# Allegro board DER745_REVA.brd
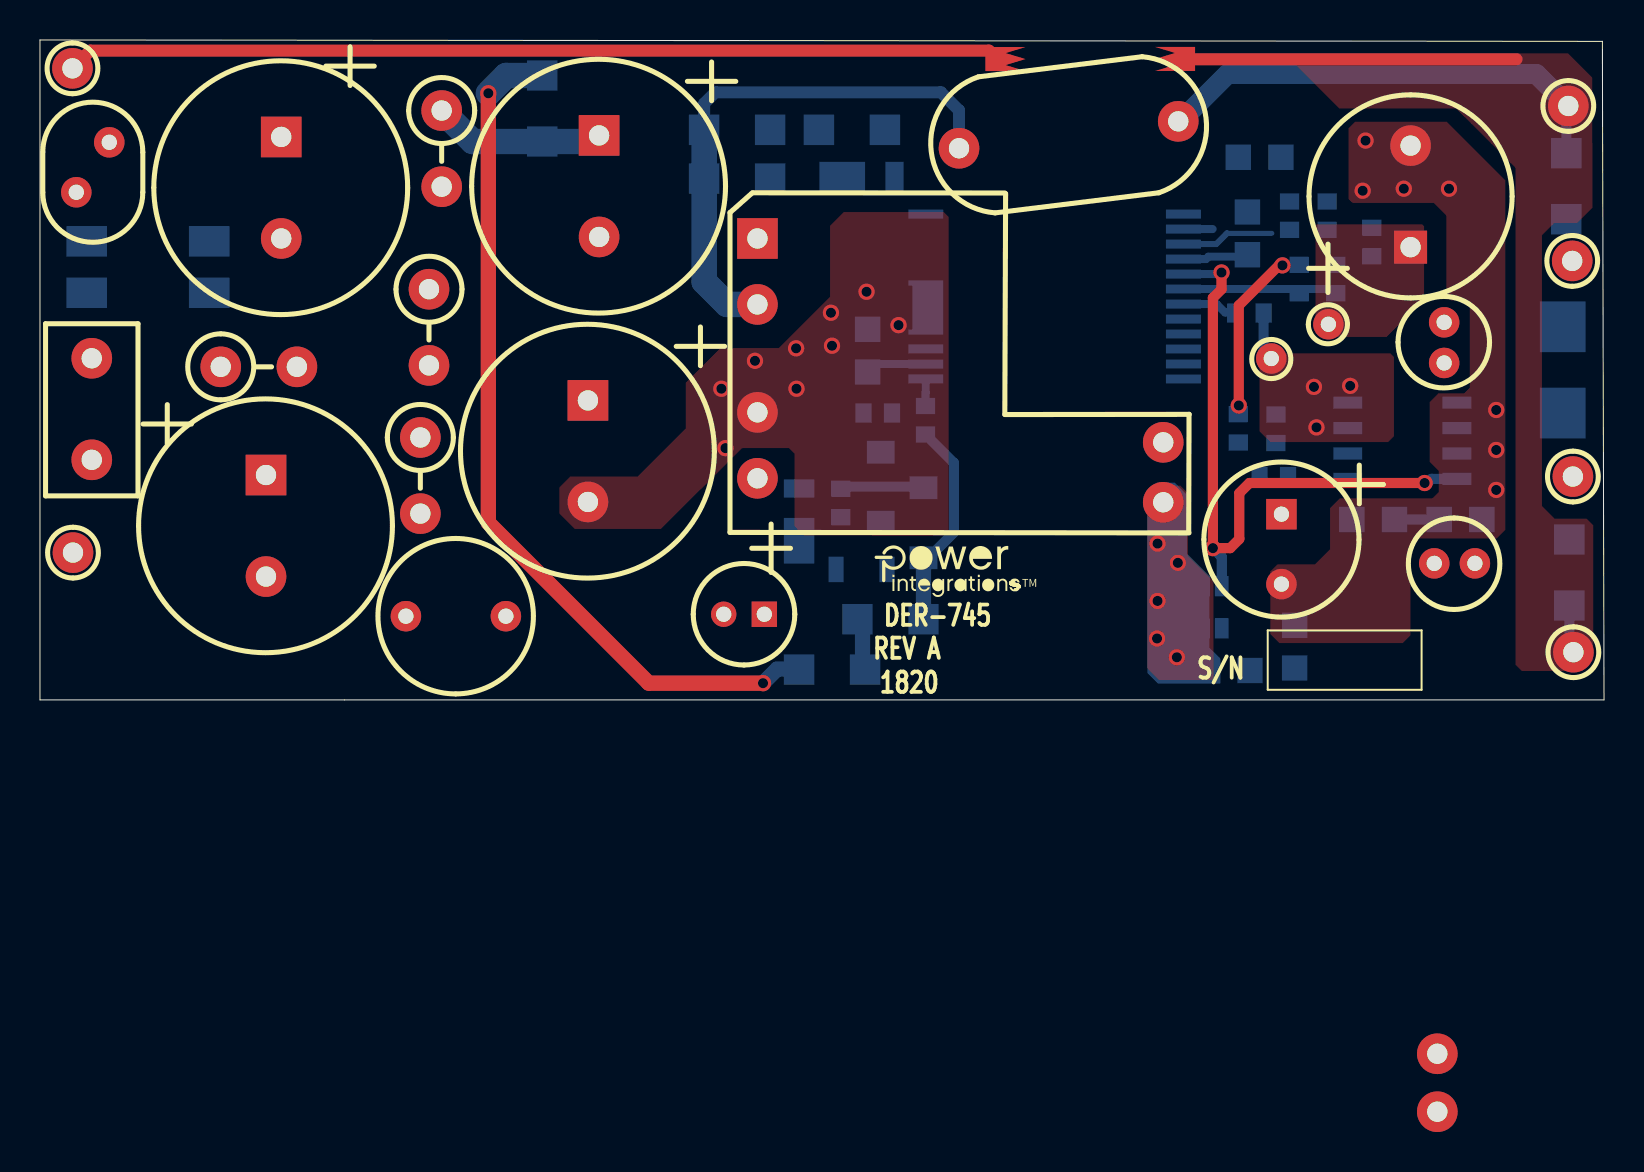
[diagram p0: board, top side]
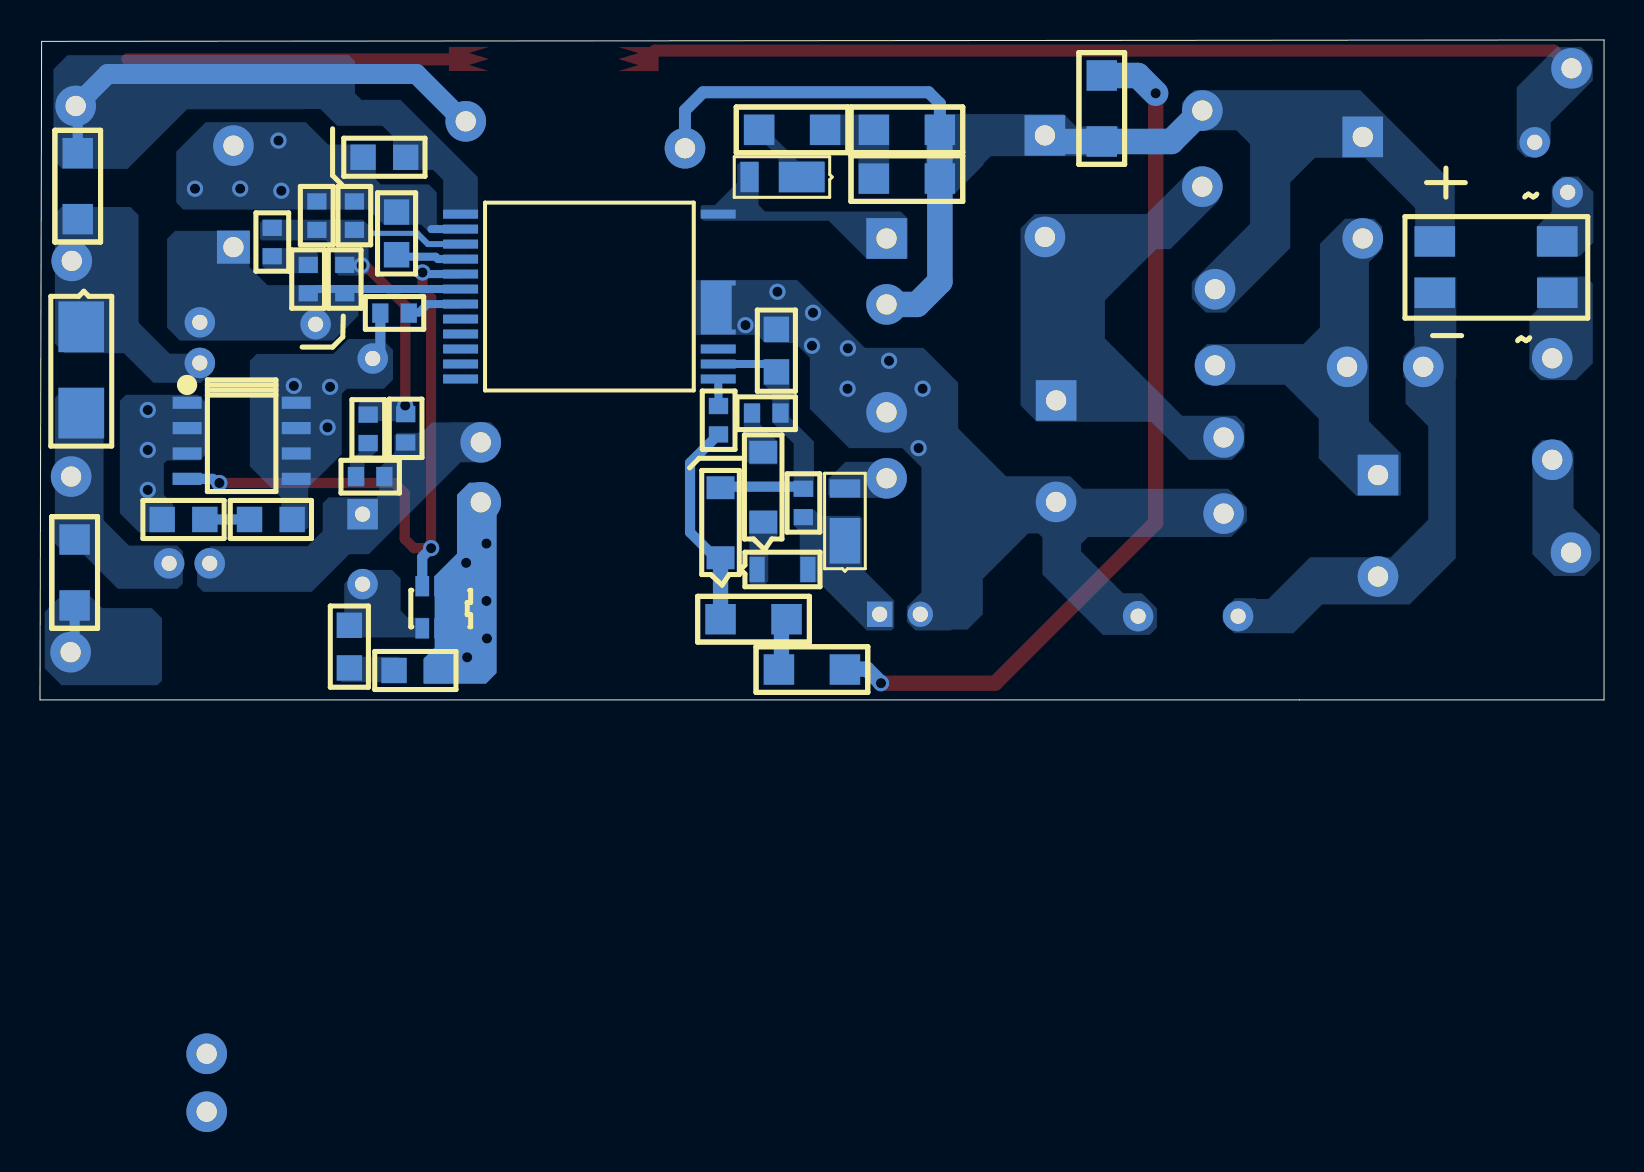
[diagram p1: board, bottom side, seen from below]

Outline 78.24 x 33.02 mm; copper layers: TOP, BOTTOM. Coordinates in mm from the lower left corner of the outline.
Outline path: 0,33.02 0,0 78.24,0 78.16,32.95 0,33.02

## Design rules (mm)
constraint set DEFAULT: min track width 0.508

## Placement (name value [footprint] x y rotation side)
BR1  B10S-G  [PISMSOIC4]  2.34 20.37 90 bottom
C1  22 uF  [PIPOLCAPCLYD500LS200040]  12.07 28.17 270 top
C2  22 uF  [PIPOLCAPCLYD500LS200040]  11.31 11.25 270 top
C3  22 uF  [PIPOLCAPCLYD500LS200040]  27.97 28.24 270 top
C4  22 uF  [PIPOLCAPCLYD500LS200040]  27.41 14.99 270 top
C5  1000 pF  [PISMC1206]  33.22 26.09 0 bottom
C6  22  uF  [PIPOLCAPCLYD200LS80030]  36.23 4.29 180 top
C7  4.7 uF  [PISMC0805]  41.4 16.41 90 bottom
C8  470 pF  [PINPCAPRAD455X275435030]  56.94 28.95 187 top
C9  1 nF  [PISMC0805]  65.62 9.03 0 bottom
C10  680 uF  [PIPOLCAPCYLD400LS200040]  68.56 22.65 90 top
C11  1 nF  [PISMC0805]  62.76 1.6 90 bottom
C12  560 uF  [PIPOLCAPCYLD315LS138D030]  62.1 9.29 270 top
C13  2.2 uF  [PISMC0805]  60.4 24.41 270 bottom
C14  330 pF  [PISMC0603]  62.51 24.94 270 bottom
C15  2.2 nF  [PISMC0603]  66.62 22.2 90 bottom
C16  2.2 nF  [PISMC0603]  61.82 12.85 90 bottom
C17  2.2 uF  [PISMC1206]  76.35 24.05 90 bottom
C18  2.2 uF  [PISMC1206]  76.5 8.03 270 bottom
D1  DFLR1600-7  [PISMDDFLR120012]  40.11 26.16 180 bottom
D2  BAV21W-7-F  [PI_SM_SOD-123_12]  44.2 7.11 90 bottom
D3  DFLR1200-7  [PISMDDFLR120012]  37.97 7.94 270 bottom
D4  BAV21WS-7-F  [PISMSOD323]  42.37 6.53 180 bottom
F1  1 A  [PI_RST_MICROFUSE]  2.59 12.01 90 top
FL1  Hole_30mils  [PI_HOLE_30MIL]  64.45 18.8 270 top
FL2  Hole_30mils  [PI_HOLE_30MIL]  61.59 17.08 0 top
L1  330 uH  [PICHOKETOKINVD345H453LS197D030]  18.31 4.19 0 top
L2  10 uH  [PI_CHOKE_TOKIN_1]  70.24 18.89 270 top
L3  10 uH  [PI_CHOKE_TOKIN_1]  69.75 6.83 0 top
LINE  WHT  [PITPKEYSTONE100X100]  1.63 31.6 0 top
NEUTRAL  RED  [PITPKEYSTONE100X100]  1.65 7.37 0 top
NOREF  -  []  -213.36 -144.78 0 top
NOREF#2  -  []  -135.54 54.23 0 top
NOREF#3  -  []  0 0 0 top
NOREF#4  -  []  41.2 7.62 0 top
NOREF#5  -  []  78.16 32.95 270.1 top
Q1  AO6420  [PISMSOT236_SHORT1256]  57.24 5.69 0 bottom
Q2  AO4486  [PISMSO8]  70.88 14.87 270 bottom
R1  620 k  [PI12WVRESD180LS150D040]  19.46 20.55 270 top
R2  620 k  [PI12WVRESD180LS150D040]  9.04 16.67 0 top
R3  620 k  [PI12WVRESD180LS150D040]  20.1 29.49 270 top
R4  620 k  [PI12WVRESD180LS150D040]  19.03 13.13 270 top
R5  3.30 M  [PISMR1206]  25.12 27.94 90 bottom
R6  3.30 M  [PISMR1206]  37.97 1.52 0 bottom
R7  3 M  [PISMR1206]  40.89 4.04 0 bottom
R8  200 k  [PISMR1206]  33.22 28.52 0 bottom
R9  68  [PISMR1206]  38.96 28.52 0 bottom
R10  100 k  [PISMR0603]  44.3 13.28 90 bottom
R11  6.2 k  [PISMR0603]  40.06 9.14 90 bottom
R12  36  [PISMR0603]  42.62 14.35 180 bottom
R13  30  [PISMR0805]  69.99 9.03 0 bottom
R14  62  [PISMR0805]  58.39 1.47 0 bottom
R15  47  [PISMR0603]  59.79 19.35 0 bottom
R16  33.2 k  [PISMR0603]  64.39 24.94 270 bottom
R17  0.02  [PISMR0805]  62.08 27.15 180 bottom
R18  100  [PISMR0603]  64.82 21.77 270 bottom
R19  1.20 M  [PISMR0603]  62.99 21.77 270 bottom
R20  100  [PISMR0603]  62.43 11.18 180 bottom
R21  133 k  [PISMR0603]  59.94 14.3 270 bottom
RT1  10  [PI_RAD_276DX197T_LS100D025]  2.64 25.4 90 top
T1  EE1621  [PI_BOBBIN_EE1621_8P]  35.89 23.09 0 top
U1  INN3672C  [PI_IC_INSOP_24D]  57.2 24.31 180 bottom
UNK5V  RED  [PITPKEYSTONE100X100]  76.68 11.18 0 top
UNK5VRTN  WHT  [PITPKEYSTONE100X100]  76.71 2.39 0 top
UNK12V  YEL  [PITPKEYSTONE100X100]  76.65 21.97 0 top
UNK12VRTN  BLK  [PITPKEYSTONE100X100]  76.45 29.72 0 top
VR1  MMSZ5231B-7-F  [PI_SM_SOD-123_12]  42.06 8.89 90 bottom
VR2  SMAZ8V2-13-F  [PISMDO214AC12]  76.17 18.67 270 bottom

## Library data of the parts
BR1 = DIODE BRIDGE_~~+-: alternate symbols: (pi_sm_soic4_slot)
C1-C4 = CAP POL: alternate symbols: (pipolcapclyd500ls200040630lh)
C5 C7-C9 C11 C13-C18 = CAP NP
C6 = CAP POL: alternate symbols: (pipolcapclyd200ls80030h)
C10 = CAP POL
C12 = CAP POL: alternate symbols: (pipolcapcyld315ls138d030h)
D1-D4 = DIODE
F1 = FUSE: alternate symbols: (pirstmicrofusehoz)
FL1 FL2 = FlyingLead
L1-L3 = INDUCTOR
LINE NEUTRAL UNK5V UNK5VRTN UNK12V UNK12VRTN = TESTPOINT
Q1 = FET_N_DGS
Q2 = FET_N_SGD_123_4_5678
R1-R4 = R: alternate symbols: (pi12wvresd180ls200d040,pi12wvresd180ls250d040,pi12wresd180ls675d040)
R5-R21 = R
RT1 = THERMISTOR
T1 = BEE16_8P/GENERIC
U1 = DEV_Inno3EP
VR1 VR2 = DIODE_ZENER

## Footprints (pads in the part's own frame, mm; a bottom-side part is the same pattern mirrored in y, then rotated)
PI12WVRESD180LS150D040
  round 2.032 hole 1.016: 1(0,0) 2(3.81,0)
PI_BOBBIN_EE1621_8P
  rect 2.032x2.032 hole 1.016: 1(0,0)
  round 2.032 hole 1.016: 2(0,-3.3) 3(0,-8.7) 4(0,-12) 5(20.3,-13.2) 6(20.3,-10.2) 7(34.011,-43.692) 8(34.011,-40.792)
PI_CHOKE_TOKIN_1
  round 1.524 hole 0.762: 1(0,0) 2(2.032,0)
PI_HOLE_30MIL
  round 1.524 hole 0.762: 1(0,0)
PI_IC_INSOP_24D
  rect 1.75x0.45 smd: 1(0,0) 2(0,-0.749) 3(0,-1.501) 4(0,-2.25) 5(0,-3) 6(0,-3.749) 7(0,-4.501) 8(0,-5.25) 9(0,-6) 10(0,-6.749) 11(0,-7.501) 12(0,-8.25) 13(12.89,-8.25) 14(12.89,-7.501) 15(12.89,-6.749) 24(12.89,0)
  custom 0.437x0.437 smd: 16(12.89,-4.671)
PI_RAD_276DX197T_LS100D025
  round 1.524 hole 0.762: 1(0,0.825) 2(2.5,-0.825)
PI_RST_MICROFUSE
  round 2.032 hole 1.016: 1(0,0) 2(5.08,0)
PI_SM_SOD-123_12
  rect 1.143x1.397 smd: 1(0,0) 2(3.505,0)
PICHOKETOKINVD345H453LS197D030
  round 1.524 hole 0.762: 1(0,0) 2(5.001,0)
PINPCAPRAD455X275435030
  round 2.032 hole 1.016: 1(0,0) 2(11.049,0)
PIPOLCAPCLYD200LS80030
  rect 1.27x1.27 hole 0.762: 1(0,0)
  round 1.27 hole 0.762: 2(2.032,0)
PIPOLCAPCLYD500LS200040
  rect 2.032x2.032 hole 1.016: 1(0,0)
  round 2.032 hole 1.016: 2(5.08,0)
PIPOLCAPCYLD315LS138D030
  rect 1.524x1.524 hole 0.762: 1(0,0)
  round 1.524 hole 0.762: 2(3.5,0)
PIPOLCAPCYLD400LS200040
  rect 1.651x1.651 hole 1.016: 1(0,0)
  round 2.032 hole 1.016: 2(5.08,0)
PISMC0603
  rect 0.813x0.965 smd: 1(0,0) 2(1.422,0)
PISMC0805
  rect 1.27x1.27 smd: 1(0,0) 2(2.134,0)
PISMC1206
  rect 1.524x1.524 smd: 1(0,0) 2(3.302,0)
PISMDDFLR120012
  rect 2.286x1.524 smd: 1(-0.025,0)
  rect 0.914x1.524 smd: 2(-2.642,0)
PISMDO214AC12
  rect 2.54x2.286 smd: 1(0,0) 2(4.318,0)
PISMR0603
  rect 0.813x0.965 smd: 1(0,0) 2(1.422,0)
PISMR0805
  rect 1.27x1.27 smd: 1(0,0) 2(2.134,0)
PISMR1206
  rect 1.524x1.524 smd: 1(0,0) 2(3.302,0)
PISMSO8
  rect 0.61x1.448 smd: 1(0,0) 2(1.27,0) 3(2.54,0) 4(3.81,0) 5(3.81,5.461) 6(2.54,5.461) 7(1.27,5.461) 8(0,5.461)
PISMSOD323
  rect 0.762x1.27 smd: 1(0,0) 2(2.54,0)
PISMSOIC4
  rect 1.524x2.032 smd: 1(0,0) 2(2.57,0) 3(2.57,6.129) 4(0,6.129)
PISMSOT236_SHORT1256
  rect 0.686x1.016 smd: (0,2.108) (0.94,0) (0.94,2.108) 1(0,0) 3(1.88,0) 4(1.88,2.108)
PITPKEYSTONE100X100
  round 2.032 hole 1.016: 1(0,0)

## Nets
NC8: U1.8
NC9: U1.9
NC10: U1.10
NC11: U1.11
NC12: U1.12
NC15: U1.15
N11050040: C17.1 L2.2 UNK12V.1 VR2.1
N11050316: BR1.3 C1.1 C3.1 C5.1 C8.2 R1.1 R3.1 R5.1 R8.1 T1.2
N11050566: C5.2 R8.2 R9.1
N11050744: BR1.1 F1.2
N11050756: BR1.2 RT1.1
N11050878: D1.1 R9.2
N11050972: C14.2 C15.2 C16.2 R16.2 R19.1 R21.1 U1.3
N11051112: D1.2 T1.1 U1.24
N11051256: R15.1 U1.7
N11051362: C6.1 D3.1 D4.2 R11.1
N11051472: D4.1 VR1.1
N11051658: C7.1 D2.2 R11.2 R12.2 U1.14
N11051742: C4.2 C6.2 C7.2 L1.2 R4.2 T1.3 U1.16
N11051898: LINE.1 RT1.2
N11051902: F1.1 NEUTRAL.1
N11062996: C9.1 FL2.1 Q2.5 Q2.6 Q2.7 Q2.8 R15.2
N11063539: C10.1 FL1.1 L2.1 R18.2 R19.2 U1.6
N11067713: R10.2 U1.13(VPIN)
N11070094: C8.1 C17.2 C18.2 R17.2 U1.1 UNK5VRTN.1 UNK12VRTN.1
N11075733: C11.1 R14.2
N11083581: C10.2 C11.2 C12.2 C13.1 C14.1 Q1.4(S) Q2.1 Q2.2 Q2.3(S3) R13.2 R16.1 R17.1 U1.2
N11083861: Q1.3 Q2.4 U1.5
N11101991: C12.1 L3.1 R20.2 R21.2 T1.6
N11104379: R12.1 VR1.2
N11115969: C9.2 R13.1
N11124964: D3.2 T1.4
N11129285: Q1.1 R14.1 T1.5
N11132220: C13.2 U1.4
N11135486: C15.1 R18.1
N11135939: C18.1 L3.2 UNK5V.1 VR2.2
N11142568: C16.1 R20.1
N11149792: BR1.4 C2.2 L1.1 R2.1
N11149826: C1.2 C2.1 R1.2 R2.2
N11150103: C3.2 C4.1 R3.2 R4.1
N11155318: R5.2 R6.1
N11155322: R6.2 R7.1
N11155751: D2.1 R7.2 R10.1

Pads without a net: T1 7 8

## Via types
v1: diameter 0.813, hole 0.508, TOP to BOTTOM, 31 vias

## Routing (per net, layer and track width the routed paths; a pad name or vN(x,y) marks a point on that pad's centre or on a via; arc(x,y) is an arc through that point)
N11050316: length 35.9
  BOTTOM w0.6: R8.1 33.22,29.84 33.79,30.4 45.07,30.4 45.97,29.5 C8.2
  BOTTOM w1.27: R3.1 21.64,27.94 R5.1 27.66,27.94 C3.1 ; T1.2 34.36,19.79 33.22,20.93 C5.1 R8.1
N11050972: length 12.7
  TOP w0.508: v1(62.15,21.74) 61.98,21.74 59.97,19.74 v1(59.97,14.73)
  BOTTOM w0.25: 61.62,23.34 59.37,23.34
  BOTTOM w0.3: 59.37,23.34 58.84,22.81 U1.3
N11051256: length 2.8
  BOTTOM w0.4: R15.1 59.77,19.38 59.29,19.38 58.86,19.81 U1.7
N11051658: length 7.3
  BOTTOM w0.4: U1.14 41.8,16.81 C7.1
  BOTTOM w0.508: D2.2 44.15,10.67 40.16,10.67 R11.2
N11051742:
  vias: v1(34.09,15.57) v1(34.29,12.6) v1(35.77,16.97) v1(37.82,17.59) v1(37.84,15.57) v1(39.57,19.37) v1(39.62,17.72) v1(41.35,20.42) v1(42.95,18.75)
N11051898: length 46.8
  TOP w0.6: LINE.1 2.51,32.49 47.47,32.49 47.85,32.11
N11062996: length 2.4
  BOTTOM w0.508: R15.2 61.21,17.46 FL2.1
  vias: v1(63.73,15.66) v1(63.86,13.64) v1(65.54,15.71)
N11063539: length 7.1
  BOTTOM w0.4: 64.31,20.56 U1.6
N11067713: length 1.4
  BOTTOM w0.4: U1.13 44.31,15.38 44.3,15.36 R10.2
N11070094: length 42.4
  TOP w0.6: 73.86,32.05 57.43,32.05
  BOTTOM w0.508: UNK12VRTN.1 76.35,29.62 C17.2 ; C18.2 76.5,2.59 UNK5VRTN.1
  BOTTOM w1: C8.1 57.04,28.95 59.41,31.32 74.85,31.32 UNK12VRTN.1
N11083581: length 1.5
  BOTTOM w0.4: U1.2 58.66,23.56
  vias: v1(66.17,25.48) v1(66.31,27.98) v1(68.22,25.58) v1(70.48,25.58) v1(72.85,14.51) v1(72.85,12.51) v1(72.85,10.51)
N11083861: length 33
  TOP w0.508: v1(69.27,10.85) 60.5,10.85 59.99,10.34 59.99,8.05 59.54,7.59 v1(58.67,7.59) 58.67,20.12 59.11,20.55 v1(59.11,21.39)
  BOTTOM w0.4: v1(59.11,21.39) 58.98,21.39 58.9,21.31 U1.5
  BOTTOM w0.508: v1(69.27,10.85) 69.4,10.85 69.61,11.06 Q2.4 ; v1(58.67,7.59) 59.12,7.15 Q1.3
N11115969: length 2.2
  BOTTOM w0.508: C9.2 R13.1
N11129285:
  vias: v1(55.91,7.82) v1(55.91,4.95) v1(55.88,3.07) v1(56.92,6.86) v1(56.87,2.13)
N11132220: length 3.3
  BOTTOM w0.4: C13.2 60.3,22.17 58.45,22.17 58.33,22.06 U1.4
N11155318: length 43.7
  TOP w0.762: v1(36.17,0.84) 30.45,0.84 22.43,8.86 v1(22.43,30.35)
  BOTTOM w0.762: v1(36.17,0.84) 36.87,1.54 37.95,1.54 R6.1
  BOTTOM w1.27: v1(22.43,30.35) 23.32,31.24 R5.2
N11155322: length 2.7
  BOTTOM w0.762: R7.1 41.15,3.78 41.15,1.65 R6.2
N11155751: length 10.6
  BOTTOM w0.508: D2.1 44.45,7.11 45.72,8.38 45.72,11.86 R10.1
  BOTTOM w0.762: D2.1 R7.2

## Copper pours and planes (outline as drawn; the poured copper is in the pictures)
N11050040 on BOTTOM: 70.15,17.32 71.75,17.32 73.3,18.87 73.3,24.26 73.71,24.66 77.17,24.66 77.5,24.33 77.5,17.83 77.01,17.35 74.04,17.35 72.57,15.88 70.18,15.88 69.72,16.33 69.72,16.89
N11050316 on BOTTOM: 24.31,28.7 26.42,28.7 27.03,29.31 33.88,29.31 33.93,29.26 33.93,25.3 32.51,25.3 31.04,26.77 31.04,26.85 30.68,27.2 24.43,27.2 24.28,27.36 24.28,28.68
N11050316 on BOTTOM: 20.5,30.51 12.19,30.51 7.47,25.78 7.47,22.17 9.45,22.17 9.45,24.61 11.96,27.13 14.45,27.13 15.7,25.88 15.7,22.61 18.92,19.38 19.91,19.38 20.62,20.09 20.62,20.9 17.7,23.83 17.7,27.81 18.39,28.5 20.95,28.5 21.11,28.65 21.11,29.9
N11050566 on BOTTOM: 39.73,29.29 39.73,27.76 38,27.76 37.3,27.06 37.3,25.36 37.26,25.32 35.79,25.32 35.76,25.35 35.76,29.29
N11050744 on BOTTOM: 3.3,21.18 0.91,21.18 0.56,20.83 0.56,16.84 1.4,16 3.17,16 3.73,16.56 3.73,19.13 3.28,19.58 3.28,21.16
N11050756 on BOTTOM: 3.33,22.2 1.22,22.2 0.53,22.89 0.53,25.43 1.3,26.19 2.11,26.19 2.62,25.68 2.62,24.43 3.38,23.67 3.38,22.25
N11050878 on BOTTOM: 43.03,29.27 43.01,29.29 42.01,29.29 41.5,29.29 41.5,28.14 40.34,26.97 39.04,26.97 38.96,26.9 38.96,25.4 41.3,25.4 41.3,27.15 41.91,27.76 43.03,27.76
N11050972 on BOTTOM: 62.31,13.94 62.31,14.81 62,15.11 59.97,15.11 59.59,14.73 59.59,13.94
N11050972 on BOTTOM: 61.49,23.44 61.49,23.24 61.8,22.94 61.8,21.44 62,21.23 63.3,21.23 63.5,21.44 63.5,22.56 63.93,22.99 67.13,22.99 67.23,23.09 67.23,23.88 67.08,24.03 62.08,24.03
N11051112 on BOTTOM: 41.96,24.43 35.18,24.43 34.82,24.08 34.82,22.07 36.88,22.07 38.79,23.98 45.06,23.98 45.19,24.1 45.19,24.69 45.12,24.75 44.49,24.75 43.36,25.88 43.36,26.77 43.21,26.92 42.34,26.92 42.29,26.87 42.29,24.77
N11051362 on BOTTOM: 40.23,5.89 40.22,5.88 39.28,5.88 36.88,3.48 35.64,3.48 35.51,3.61 35.51,4.98 37.11,6.58 37.11,9.08 37.24,9.21 39.2,9.21 39.5,9.5 40.51,9.5 40.51,8.71 40.23,8.43
N11051472 on BOTTOM: 41.33,8.26 41.81,7.77 41.81,5.94 42.04,5.71 42.6,5.71 42.74,5.85 42.74,7.53 42.75,7.54 42.75,9.47 42.72,9.5 41.35,9.5 41.33,9.47
N11051658 on BOTTOM: 42.04,17.04 42.04,15.8 41.61,15.37 41.61,13.89 40.54,12.83 40.54,10.21 40.49,10.16 39.52,10.16 39.52,12.93 40.74,14.15 40.74,17.02 40.77,17.04
N11051742 on TOP: 45.45,8.23 38.2,8.23 37.74,8.69 37.74,12.32 37.47,12.6 35.13,12.6 33.07,10.54 33.05,10.54 31.06,8.56 26.75,8.56 25.98,9.32 25.98,10.64 26.52,11.18 29.9,11.18 32.31,13.59 32.31,15.88 34.04,17.6 36.96,17.6 39.52,20.17 39.52,23.72 40.21,24.41 45.21,24.41 45.45,24.17
N11051742 on BOTTOM: 42.37,18.26 41.96,17.86 40.46,17.86 39.73,17.12 39.73,14.55 37.77,12.6 35.1,12.6 34.15,11.65 34.15,5.38 34.87,4.66 34.87,3.91 34.44,3.48 32.66,3.48 32.63,3.52 31.84,3.52 31.08,4.28 31.08,6.06 28.8,8.33 28.3,8.33 28.09,8.13 28.09,6.27 25.07,3.25 22.73,3.25 22.36,3.62 22.36,4.58 23.11,5.33 24.05,5.33 26.16,7.44 26.16,7.8 25.81,8.15 18.66,8.15 17.87,8.94 17.87,9.64 18.8,10.57 26.07,10.57 26.7,11.19 29.91,11.19 32.31,13.59 32.31,15.88 34.05,17.61 36.97,17.61 40.36,21.01 45.42,21.01 45.42,18.26
N11051898 on TOP (solid shape): 48.29,32.36 49.29,32.06 48.29,31.76 49.29,31.46 47.29,31.46 47.29,32.66 49.29,32.66
N11051898 on BOTTOM: 1.14,32.66 2.36,32.66 4.37,30.66 4.37,27.58 3.94,27.15 3.35,27.15 2.67,27.84 2.67,28.88 0.56,30.99 0.56,32.08
N11051902 on BOTTOM: 2.13,13 3.1,13 3.58,12.52 3.58,7.29 2.49,6.2 0.99,6.2 0.2,6.99 0.2,8.28 1.52,9.6 1.52,12.4
N11062996 on TOP: 61.01,17.32 61.01,13.44 61.54,12.9 67.45,12.9 67.73,13.18 67.73,17.16 67.54,17.35 62.31,17.35 61.82,17.83 61.52,17.83
N11062996 on BOTTOM: 61.14,18.06 62.81,18.06 63.56,17.31 67.4,17.31 67.74,16.97 67.74,11.68 66.17,10.11 66.17,8.48 66.09,8.41 65.05,8.41 64.82,8.64 64.82,10.62 63.14,12.29 63.14,15.32 62.89,15.57 61.04,15.57 60.58,16.03 60.58,17.5
N11063539 on TOP: 63.8,18.57 63.8,23.72 63.88,23.8 69.14,23.8 69.24,23.7 69.24,20.04 67.36,18.16 64.21,18.16
N11063539 on BOTTOM: 71.88,18.62 71.88,23.06 71.48,23.47 67.87,23.47 67.75,23.36 67.75,21.65 66.85,20.75 62.18,20.75 62.1,20.68 62.1,20.4 62.31,20.19 62.31,19.23 63.55,17.98 71.25,17.98
N11070094 on TOP (solid shape): 57.78,31.47 55.78,31.47 56.78,31.77 55.78,32.07 56.78,32.37 55.78,32.67 57.78,32.67
N11070094 on TOP: 74.12,1.45 73.81,1.75 73.81,26.62 70.84,29.59 65,29.59 62.53,32.05 62.53,32.33 62.56,32.36 76.43,32.36 77.65,31.14 77.65,27.86 77.66,27.85 77.66,24.63 76.89,23.85 75.74,23.85 75.13,23.24 75.13,9.7 75.77,9.07 77.37,9.07 77.7,8.74 77.7,2.01 77.14,1.45
N11070094 on BOTTOM: 72.14,0.97 72.36,0.74 77.17,0.74 78,1.57 78,4.39 77.14,5.26 75.79,5.26 75.13,4.6 72.64,4.6 72.14,4.09
N11070094 on BOTTOM: 60.2,30.02 62.15,30.02 62.48,30.35 62.48,31.95 62.79,32.26 76.86,32.26 77.57,31.55 77.57,27.03 77.11,26.57 73.86,26.57 70.88,29.55 65.04,29.55 65.02,29.57 64.21,29.57 63.37,28.73 61.11,28.73 60.58,28.19 60.58,26.52 58.57,26.52 58.06,26.01 58.06,24.08 56.34,24.08 56.34,26.16
N11075733 on BOTTOM: 60.1,1.98 60.1,1.02 60.22,0.89 63.14,0.89 63.32,1.07 63.32,1.98 63.14,2.16 60.27,2.16
N11083581 on TOP: 70.35,20.23 70.59,19.99 71.32,19.99 71.53,19.79 71.53,15.62 71.25,15.34 69.95,15.34 69.52,14.91 69.52,11.91 69.98,11.46 69.98,10.41 69.65,10.08 65.02,10.08 64.54,9.6 64.54,7.54 63.78,6.78 61.9,6.78 61.54,6.43 61.54,3.3 62,2.84 68.17,2.84 68.55,3.23 68.55,7.67 68.96,8.08 72.87,8.08 73.3,8.51 73.3,26 70.37,28.93 65.79,28.93 65.46,28.6 65.46,25.07 65.66,24.87 69.72,24.87 70.35,24.24
N11083581 on BOTTOM: 71.88,11.98 72.04,11.82 72.04,10.26 71.58,9.8 71.58,8.59 71.77,8.39 73.3,8.39 74.24,9.34 74.24,14.93 74.23,14.94 74.23,14.97 73.94,15.27 70.33,15.27 69.98,14.91 69.98,12.26 70.26,11.98
N11083581 on BOTTOM: 58.7,4.04 58.7,3.25 58.83,3.12 62.84,3.12 63.02,3.3 63.02,5.82 62.33,6.5 60.63,6.5 60.2,6.07 60.2,4.47 59.84,4.11 58.78,4.11
N11083581 on BOTTOM: 61.8,24.54 61.04,23.77 59.16,23.77 58.75,23.37 58.19,23.37 58.19,23.65 58.39,23.85 58.39,25.4 58.79,25.79 61.19,25.79 61.44,26.05 61.44,27.79 63.83,27.79 64.95,28.91 69.95,28.91 71.42,27.43 71.42,24.89 71.07,24.54
N11101991 on BOTTOM: 64.1,8.45 64.86,7.68 69.71,7.68 70.38,7.01 70.38,5.71 70.08,5.41 64.64,5.41 62.76,7.29 61.8,7.29 57.2,11.89 55.88,11.89 55.32,12.45 55.32,13.51 55.7,13.89 57.68,13.89 57.7,13.88 58.64,13.88 59.16,13.36 60.38,13.36 60.5,13.23 60.5,12.37 61.26,11.61 61.26,10.29 61.42,10.13 63.8,10.13 64.1,9.84
N11104379 on BOTTOM: 43.03,14.83 42.21,14.83 42.21,13.79 41.35,12.93 41.35,11.79 42.72,11.79 43.03,12.09
N11124964 on BOTTOM: 35.61,11.91 35.28,11.58 35.28,10.44 35.61,10.11 38.66,10.11 38.81,10.26 38.81,11.05 37.95,11.91
N11129285 on BOTTOM (solid shape): 57.38,10.26 57.38,7.32 58.5,6.2 58.5,2.59 58.52,2.59 59.05,2.06 59.05,0.84 59.03,0.81 55.93,0.81 55.4,1.35 55.4,10.41 55.85,10.87 56.77,10.87
N11129285 on TOP: 57.05,10.72 55.7,10.72 55.4,10.41 55.4,1.57 55.98,0.99 58.62,0.99 58.7,1.07 58.7,5.94 57.43,7.21 57.43,10.34
N11135486 on BOTTOM: 64.62,22.61 67.03,22.61 67.11,22.53 67.11,21.69 66.76,21.35 64.35,21.35 64.34,21.36 64.34,22.33
N11135939 on BOTTOM: 75.23,15.42 77.19,15.42 77.5,15.11 77.5,7.82 76.96,7.29 76.07,7.29 74.35,5.56 71.35,5.56 71.09,5.82 71.09,7.44 71.37,7.72 73.79,7.72 75.06,8.99 75.06,15.24
N11142568 on BOTTOM: 61.39,13.18 61.39,12.45 62,11.84 62,10.72 62.71,10.72 62.74,10.74 62.74,11.91 62.28,12.37 62.28,13.11 62.2,13.18
N11149792 on BOTTOM: 7.39,21.16 9.5,21.16 9.5,18.19 9.47,18.16 9.47,17.75 10.03,17.2 10.03,16.15 9.35,15.47 8.05,15.47 7.39,16.13
N11149792 on BOTTOM: 10.67,7.14 14.71,7.14 16.79,5.05 17.4,5.05 17.44,5.09 18.45,5.09 19.08,4.47 19.08,3.91 18.5,3.34 15.53,3.34 14.1,4.78 9.73,4.78 7.42,7.09 7.42,16.38 7.9,16.87 9.42,16.87 9.93,16.36 9.93,14.83 8.79,13.69 8.79,9.02
N11149826 on BOTTOM: 11.51,24.08 12.95,24.08 14.21,22.82 14.21,18.63 15.04,17.81 19.86,17.81 20.4,17.27 20.4,16.21 19.96,15.77 15.98,15.77 14.27,14.07 14.27,12.09 12.4,10.21 10.21,10.21 10.16,10.26 10.16,12.34 11.76,13.94 11.76,21.89 11.1,22.56 11.1,23.67
N11150103 on BOTTOM: 19.63,26.52 20.68,26.52 22.89,24.31 28.47,24.31 29.18,23.6 29.18,14.73 28.37,13.92 22.66,13.92 20.75,12.01 18.62,12.01 17.98,12.65 17.98,13.79 18.41,14.22 21.11,14.22 24.97,18.08 24.97,19.99 22.4,22.56 21.69,22.56 19.28,24.97 19.28,26.16

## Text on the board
Ref Des/Silkscreen Top: REV A | 1820 | DER-745 | S/N
User.5: 14.  FAB HOUSE LOGO,DATE CODE TO BE IN SILK SCREEN ONLY.DO NOT USE COPPER. | 13.  MATERIAL FR4 COPPER 2oz THICKNESS 0.062" | PLEASE DELETE THESE PINS
User.8: FIGURE | FINISHED_SIZE | 20.0 | 30.0 | 40.0 | DRILL CHART: TOP to BOTTOM | ALL UNITS ARE IN MILS | TOLERANCE_DRILL | +0.0/-0.0 | +3.0/-3.0 | PLATED | QTY | 31 | 14 | 32 | 4
